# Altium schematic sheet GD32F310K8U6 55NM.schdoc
size 127 x 101 mm
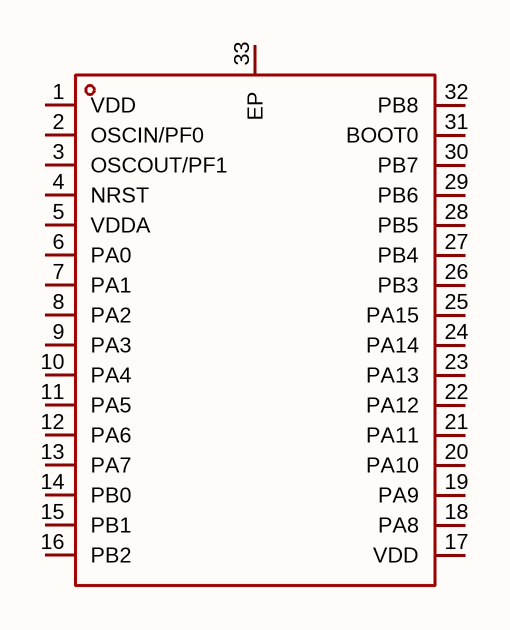
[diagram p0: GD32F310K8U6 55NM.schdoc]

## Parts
U?  gd32f310k8u6 55nm  [UFQFN-32_L5.0-W5.0-P0.50-TL-EP3.5]  (value not drawn)

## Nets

Not connected (* = marked no-connect by the designer): U? 1(VDD) 2(OSCIN/PF0) 3(OSCOUT/PF1) 4(NRST) 5(VDDA) 6(PA0) 7(PA1) 8(PA2) 9(PA3) 10(PA4) 11(PA5) 12(PA6) 13(PA7) 14(PB0) 15(PB1) 16(PB2) 17(VDD) 18(PA8) 19(PA9) 20(PA10) 21(PA11) 22(PA12) 23(PA13) 24(PA14) 25(PA15) 26(PB3) 27(PB4) 28(PB5) 29(PB6) 30(PB7) 31(BOOT0) 32(PB8) 33(EP)

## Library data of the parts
U? = gd32f310k8u6 55nm: CPU内核:ARM Cortex-M系列;CPU最大主频:72MHz;; Manufacturer: GigaDevice(兆易创新); AddInBom: yes; ModelId: e0541b9beeca4b1ebfaec6507007ed0f; ModelName: UFQFPN-32_L5.0-W5.0-H0.6-P0.50; ModelTransform: 196.85,196.85,0,0,0,0,-2.402,0.512,0; CPU Maximum Speed: 72MHz; Program Storage Size: 64KB; Program Memory Type: FLASH; Number of I/O: 39; ADC (Bit): 10bit；8bit；6bit；12bit; Voltage - Supply: 2.6V~3.6V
